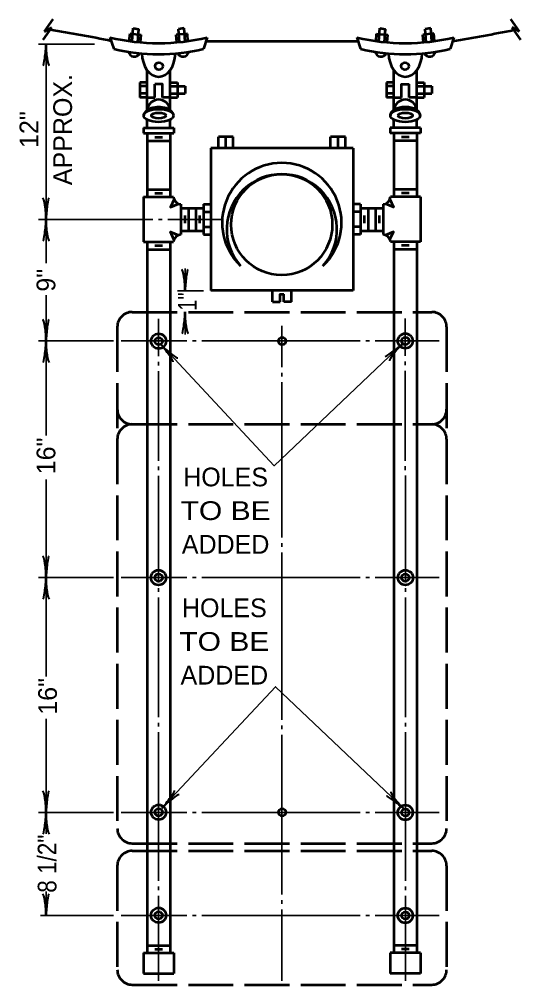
# Model space of a CAD drawing. Extents: x -1 to 679, y 1 to 441.
# Drawn here: x 144.6 to 211.6, y 193.8 to 322.8 of the extents above; entities that cross this region are included whole.
import ezdxf
from ezdxf.enums import TextEntityAlignment as Align

# ---------------------------------------------------------------- set-up
doc = ezdxf.new("R2010")
doc.units = 0
doc.linetypes.add('LONG_DASHED', pattern=[7.5, 6, -1.5])
doc.layers.add('1', color=7, linetype='Continuous', lineweight=35)

msp = doc.modelspace()

# ---------------------------------------------------------------- linework, layer by layer
at = {"layer": '1', "lineweight": 53}
for p, q in [((147.985, 321.145), (149.132, 322.783)), ((211.459, 321.145), (210.311, 322.783)), ((147.833, 320.046), (148.98, 321.684)), ((147.985, 321.145), (148.98, 321.684)), ((159.704, 319.867), (159.857, 321.61)), ((159.857, 321.61), (160.582, 321.469)), ((160.46, 319.723), (160.582, 321.469)), ((166.662, 321.582), (165.909, 321.467)), ((166.031, 319.721), (165.909, 321.467)), ((166.784, 319.836), (166.662, 321.582)), ((192.66, 319.836), (192.782, 321.582)), ((192.782, 321.582), (193.534, 321.467)), ((193.413, 319.721), (193.534, 321.467)), ((199.587, 321.61), (198.862, 321.469)), ((198.983, 319.723), (198.862, 321.469)), ((199.739, 319.867), (199.587, 321.61)), ((211.611, 320.046), (210.464, 321.684)), ((211.459, 321.145), (210.464, 321.684)), ((156.744, 320.356), (157.244, 318.856)), ((159.328, 319.875), (159.418, 320.896)), ((159.418, 320.896), (160.904, 320.695)), ((160.835, 319.707), (160.904, 320.695)), ((167.088, 320.86), (165.587, 320.692)), ((165.656, 319.708), (165.587, 320.692)), ((167.157, 319.875), (167.088, 320.86)), ((169.744, 320.356), (169.244, 318.856)), ((189.699, 320.356), (190.199, 318.856)), ((192.286, 319.875), (192.355, 320.86)), ((192.355, 320.86), (193.856, 320.692)), ((193.787, 319.708), (193.856, 320.692)), ((200.026, 320.896), (198.54, 320.695)), ((198.608, 319.707), (198.54, 320.695)), ((200.115, 319.875), (200.026, 320.896)), ((202.699, 320.356), (202.199, 318.856)), ((169.586, 319.881), (189.857, 319.881)), ((161.722, 310.652), (161.722, 315.963)), ((164.767, 310.652), (164.767, 315.963)), ((194.677, 310.652), (194.677, 315.963)), ((197.722, 310.652), (197.722, 315.963)), ((161.722, 314.356), (160.722, 314.356)), ((160.722, 314.356), (160.722, 312.356)), ((161.722, 313.856), (160.722, 313.856)), ((162.722, 312.356), (162.722, 314.106)), ((164.767, 314.356), (165.767, 314.356)), ((164.767, 313.856), (166.767, 313.856)), ((165.767, 314.356), (165.767, 312.356)), ((166.767, 313.856), (166.767, 312.856)), ((194.677, 314.356), (193.677, 314.356)), ((193.677, 314.356), (193.677, 312.356)), ((194.677, 313.856), (193.677, 313.856)), ((196.722, 312.356), (196.722, 314.106)), ((197.722, 314.356), (198.722, 314.356)), ((197.722, 313.856), (199.722, 313.856)), ((198.722, 314.356), (198.722, 312.356)), ((199.722, 313.856), (199.722, 312.856)), ((161.722, 312.856), (160.722, 312.856)), ((161.722, 312.356), (160.722, 312.356)), ((161.722, 312.356), (162.722, 312.356)), ((164.767, 312.356), (163.767, 312.356)), ((164.767, 312.856), (166.767, 312.856)), ((164.767, 312.356), (165.767, 312.356)), ((194.677, 312.856), (193.677, 312.856)), ((194.677, 312.356), (193.677, 312.356)), ((194.677, 312.356), (195.677, 312.356)), ((197.722, 312.356), (196.722, 312.356)), ((197.722, 312.856), (199.722, 312.856)), ((197.722, 312.356), (198.722, 312.356)), ((161.222, 308.298), (165.267, 308.298)), ((161.222, 308.298), (161.222, 307.548)), ((161.722, 308.298), (161.722, 309.356)), ((164.767, 308.298), (164.767, 309.356)), ((165.267, 308.298), (165.267, 307.548)), ((198.222, 308.298), (194.177, 308.298)), ((194.177, 308.298), (194.177, 307.548)), ((194.677, 308.298), (194.677, 309.356)), ((197.722, 308.298), (197.722, 309.356)), ((198.222, 308.298), (198.222, 307.548)), ((161.222, 307.548), (165.267, 307.548)), ((161.722, 307.548), (161.722, 299.048)), ((162.722, 307.048), (163.767, 307.048)), ((164.767, 307.548), (164.767, 299.048)), ((171.222, 305.57), (171.222, 307.07)), ((173.222, 307.07), (171.222, 307.07)), ((172.222, 305.57), (172.222, 307.07)), ((173.222, 305.57), (173.222, 307.07)), ((186.222, 305.57), (186.222, 307.07)), ((188.222, 307.07), (186.222, 307.07)), ((187.222, 305.57), (187.222, 307.07)), ((188.222, 305.57), (188.222, 307.07)), ((198.222, 307.548), (194.177, 307.548)), ((194.677, 307.548), (194.677, 299.048)), ((196.722, 307.048), (195.677, 307.048)), ((197.722, 307.548), (197.722, 299.048)), ((161.722, 306.548), (164.767, 306.548)), ((197.722, 306.548), (194.677, 306.548)), ((189.222, 305.57), (170.222, 305.57)), ((170.222, 305.57), (170.222, 286.536)), ((189.222, 305.57), (189.222, 286.536)), ((161.722, 300.048), (164.767, 300.048)), ((162.722, 299.548), (163.767, 299.548)), ((197.722, 300.048), (194.677, 300.048)), ((196.722, 299.548), (195.677, 299.548)), ((161.222, 299.048), (165.221, 299.048)), ((161.222, 299.048), (161.222, 293.048)), ((166.222, 298.07), (166.222, 294.025)), ((169.222, 298.07), (169.222, 294.036)), ((169.222, 298.07), (170.222, 298.07)), ((190.222, 298.07), (189.222, 298.07)), ((190.222, 298.07), (190.222, 294.036)), ((193.222, 298.07), (193.222, 294.025)), ((198.222, 299.048), (194.223, 299.048)), ((198.222, 299.048), (198.222, 293.048)), ((166.222, 297.57), (169.222, 297.57)), ((167.222, 297.57), (167.222, 294.525)), ((168.222, 297.57), (168.222, 294.525)), ((169.222, 297.07), (170.222, 297.07)), ((190.222, 297.07), (189.222, 297.07)), ((190.222, 297.57), (193.222, 297.57)), ((191.222, 297.57), (191.222, 294.525)), ((192.222, 297.57), (192.222, 294.525)), ((166.722, 296.57), (166.722, 295.525)), ((168.722, 296.57), (168.722, 295.525)), ((190.722, 296.57), (190.722, 295.525)), ((192.722, 296.57), (192.722, 295.525)), ((166.222, 294.525), (169.222, 294.525)), ((169.222, 295.036), (170.222, 295.036)), ((190.222, 295.036), (189.222, 295.036)), ((190.222, 294.525), (193.222, 294.525)), ((161.222, 293.048), (165.217, 293.048)), ((161.722, 293.048), (164.767, 293.048)), ((164.767, 293.048), (164.767, 283.672)), ((169.222, 294.036), (170.222, 294.036)), ((190.222, 294.036), (189.222, 294.036)), ((198.222, 293.048), (194.226, 293.048)), ((197.722, 293.048), (194.677, 293.048)), ((197.722, 293.048), (197.722, 255.048)), ((161.722, 292.048), (164.767, 292.048)), ((162.722, 292.548), (163.767, 292.548)), ((197.722, 292.048), (194.677, 292.048)), ((196.722, 292.548), (195.677, 292.548)), ((189.222, 286.536), (170.222, 286.536)), ((178.472, 285.036), (178.472, 286.536)), ((180.972, 285.036), (180.972, 286.536)), ((179.972, 285.036), (179.972, 286.036)), ((178.472, 285.036), (179.472, 285.036)), ((180.972, 285.036), (179.972, 285.036)), ((164.767, 283.672), (164.767, 212.672)), ((197.722, 255.048), (197.722, 198.048)), ((164.767, 212.672), (164.767, 198.048)), ((161.722, 199.048), (164.767, 199.048)), ((197.722, 199.048), (194.677, 199.048)), ((161.222, 198.048), (165.267, 198.048)), ((161.222, 198.048), (161.222, 195.298)), ((162.722, 198.548), (163.767, 198.548)), ((165.267, 198.048), (165.267, 195.298)), ((194.177, 198.048), (194.177, 195.298)), ((198.222, 198.048), (194.177, 198.048)), ((196.722, 198.548), (195.677, 198.548)), ((198.222, 198.048), (198.222, 195.298)), ((161.222, 195.298), (165.267, 195.298)), ((198.222, 195.298), (194.177, 195.298))]:
    msp.add_line(p, q, dxfattribs=at)
at = {"layer": '1'}
for p, q in [((154.674, 319.477), (147.199, 319.477)), ((148.199, 296.048), (148.199, 319.477)), ((162.472, 296.048), (147.199, 296.048)), ((148.199, 296.048), (148.199, 290.214)), ((163.222, 296.048), (163.722, 296.048)), ((164.472, 296.048), (171.738, 296.048)), ((166.767, 286.492), (166.767, 289.492)), ((165.767, 286.492), (169.222, 286.492)), ((163.244, 282.781), (163.244, 277.781)), ((166.767, 283.672), (166.767, 280.672)), ((196.199, 282.809), (196.199, 277.809)), ((179.722, 281.814), (179.722, 276.289)), ((147.199, 279.814), (157.222, 279.814)), ((158.222, 279.814), (167.017, 279.814)), ((166.517, 279.814), (167.017, 279.814)), ((167.767, 279.814), (168.267, 279.814)), ((169.017, 279.814), (190.177, 279.814)), ((190.927, 279.814), (191.427, 279.814)), ((192.177, 279.814), (200.722, 279.814)), ((163.244, 277.031), (163.244, 276.531)), ((196.199, 277.059), (196.199, 276.559)), ((163.244, 275.781), (163.244, 263.781)), ((179.722, 275.039), (179.722, 275.539)), ((196.199, 275.809), (196.199, 263.809)), ((179.722, 274.289), (179.722, 253.548)), ((163.244, 263.031), (163.244, 262.531)), ((196.199, 263.059), (196.199, 262.559)), ((163.221, 261.781), (163.221, 247.542)), ((196.222, 261.809), (196.222, 247.542)), ((179.722, 252.298), (179.722, 252.798)), ((179.722, 251.548), (179.722, 229.193)), ((157.222, 248.193), (147.199, 248.193)), ((158.222, 248.193), (167.017, 248.193)), ((167.767, 248.193), (168.267, 248.193)), ((169.017, 248.193), (190.177, 248.193)), ((190.927, 248.193), (191.427, 248.193)), ((200.722, 248.193), (192.177, 248.193)), ((200.722, 248.193), (192.722, 248.193)), ((163.221, 246.792), (163.221, 246.292)), ((196.222, 246.792), (196.222, 246.292)), ((163.221, 245.542), (163.221, 229.542)), ((196.222, 245.542), (196.222, 229.542)), ((163.221, 228.792), (163.221, 228.292)), ((179.722, 227.943), (179.722, 228.443)), ((196.222, 228.792), (196.222, 228.292)), ((163.221, 227.542), (163.221, 207.672)), ((179.722, 227.193), (179.722, 205.825)), ((196.222, 227.542), (196.222, 207.672)), ((147.199, 216.799), (157.222, 216.799)), ((158.222, 216.799), (167.017, 216.799)), ((167.767, 216.799), (168.267, 216.799)), ((169.017, 216.799), (190.177, 216.799)), ((190.927, 216.799), (191.427, 216.799)), ((192.177, 216.799), (200.722, 216.799)), ((179.722, 212.292), (179.722, 212.792)), ((163.221, 206.422), (163.221, 206.922)), ((196.222, 206.422), (196.222, 206.922)), ((148.199, 206.256), (148.199, 203.048)), ((163.221, 205.672), (163.221, 194.298)), ((196.222, 205.672), (196.222, 194.298)), ((179.722, 205.075), (179.722, 204.575)), ((179.722, 203.825), (179.722, 194.298)), ((157.222, 203.048), (147.449, 203.048)), ((158.222, 203.048), (167.017, 203.048)), ((167.767, 203.048), (168.267, 203.048)), ((169.017, 203.048), (190.177, 203.048)), ((190.927, 203.048), (191.427, 203.048)), ((192.177, 203.048), (200.722, 203.048))]:
    msp.add_line(p, q, dxfattribs=at)
at = {"layer": '1', "linetype": 'LONG_DASHED', "lineweight": 53}
for p, q in [((159.722, 283.672), (199.722, 283.672)), ((157.722, 281.672), (157.722, 266.672)), ((201.722, 281.672), (201.722, 266.672)), ((159.722, 268.672), (199.722, 268.672)), ((157.722, 266.672), (157.722, 214.672)), ((201.722, 266.672), (201.722, 214.672)), ((159.722, 212.672), (199.722, 212.672)), ((159.722, 211.672), (199.722, 211.672)), ((157.722, 209.672), (157.722, 195.793)), ((201.722, 209.672), (201.722, 195.793)), ((159.722, 193.793), (199.722, 193.793))]:
    msp.add_line(p, q, dxfattribs=at)
at = {"layer": '1', "lineweight": 13}
for p, q in [((179.722, 212.792), (179.722, 213.542)), ((179.722, 211.542), (179.722, 212.292))]:
    msp.add_line(p, q, dxfattribs=at)
at = {"layer": '1', "lineweight": 53}
for points in [[(163.767, 312.356), (163.767, 314.106), (162.722, 314.106)], [(195.677, 312.356), (195.677, 314.106), (196.722, 314.106)], [(165.299, 298.745), (164.814, 297.698), (165.905, 298.146)], [(194.145, 298.745), (194.63, 297.698), (193.538, 298.146)], [(165.295, 293.35), (164.81, 294.397), (165.902, 293.949)], [(194.148, 293.35), (194.633, 294.397), (193.542, 293.949)], [(161.722, 293.048), (161.722, 255.048), (161.722, 198.048)], [(194.677, 293.048), (194.677, 255.048), (194.677, 198.048)], [(179.472, 285.036), (179.472, 286.036), (179.972, 286.036)]]:
    msp.add_lwpolyline(points, dxfattribs=at)
at = {"layer": '1'}
for points in [[(148.199, 285.903), (148.199, 279.814), (148.199, 267.186)], [(163.525, 279.364), (178.678, 263.127), (195.867, 279.448)], [(148.199, 261.306), (148.199, 248.193), (148.199, 234.971)], [(163.689, 217.363), (178.842, 233.6), (196.031, 217.278)], [(148.199, 229.324), (148.199, 216.799), (148.199, 213.945)]]:
    msp.add_lwpolyline(points, dxfattribs=at)
at = {"layer": '1', "lineweight": 53}
for centre, radius in [((163.289, 316.528), 0.5), ((196.155, 316.528), 0.5), ((179.691, 295.35), 6.75), ((163.235, 279.781), 1), ((163.249, 279.781), 0.5), ((179.746, 279.789), 0.5), ((196.198, 279.809), 1), ((196.213, 279.809), 0.5), ((163.226, 248.186), 1), ((196.218, 248.186), 1), ((163.241, 248.186), 0.5), ((196.203, 248.186), 0.5), ((163.235, 216.832), 1), ((163.249, 216.832), 0.5), ((179.746, 216.825), 0.5), ((196.198, 216.804), 1), ((196.213, 216.804), 0.5), ((163.229, 203.061), 1), ((196.197, 203.038), 1), ((163.244, 203.061), 0.5), ((196.211, 203.038), 0.5)]:
    msp.add_circle(centre, radius, dxfattribs=at)
for centre, radius, start, end in [((126.005, 172.228), 150.851, 78.18089, 81.33006), ((160.338, 576.7), 260.264, 279.33196, 281.15709), ((163.244, 348.147), 28.542, 256.83593, 283.1638), ((196.199, 348.147), 28.542, 256.8362, 283.16407), ((163.244, 342.481), 24.375, 255.74997, 284.25003), ((196.199, 342.481), 24.375, 255.74997, 284.25003), ((160.006, 318.618), 0.821, 192.33045, 332.21364), ((166.485, 318.618), 0.821, 207.78636, 347.66955), ((192.958, 318.618), 0.821, 192.33045, 332.21364), ((199.438, 318.618), 0.821, 207.78636, 347.66955), ((163.244, 310.52), 1.528, 4.98578, 175.01422), ((196.199, 310.52), 1.528, 4.98578, 175.01422), ((179.701, 295.614), 7.975, 313.60282, 226.39718), ((179.701, 294.736), 7.364, 318.31863, 221.68137), ((166.317, 299.169), 1.103, 186.32364, 248.08344), ((166.317, 299.169), 1.103, 202.62687, 248.08262), ((166.317, 299.169), 1.103, 248.08344, 265.0377), ((193.126, 299.169), 1.103, 274.9623, 291.91656), ((193.126, 299.169), 1.103, 291.91656, 353.67636), ((193.126, 299.169), 1.103, 291.91738, 337.37313), ((166.314, 292.926), 1.103, 111.91656, 173.65459), ((166.314, 292.926), 1.103, 111.91738, 157.37313), ((166.314, 292.926), 1.103, 94.77118, 111.91656), ((193.13, 292.926), 1.103, 68.08344, 85.22882), ((193.13, 292.926), 1.103, 6.34541, 68.08344), ((193.13, 292.926), 1.103, 22.62687, 68.08262)]:
    msp.add_arc(centre, radius, start, end, dxfattribs=at)
at = {"layer": '1', "linetype": 'LONG_DASHED', "lineweight": 53}
for centre, start, end in [((159.722, 281.672), 90, 180), ((199.722, 281.672), 0, 90), ((159.722, 270.672), 180, 270), ((199.722, 270.672), 270, 0), ((159.722, 266.672), 90, 180), ((199.722, 266.672), 0, 90), ((159.722, 214.672), 180, 270), ((159.722, 214.672), 180, 270), ((199.722, 214.672), 270, 0), ((159.722, 209.672), 90, 180), ((199.722, 209.672), 0, 90), ((159.722, 195.793), 180, 270), ((199.722, 195.793), 270, 0)]:
    msp.add_arc(centre, 2, start, end, dxfattribs=at)
at = {"layer": '1', "lineweight": 40}
for centre, major_axis, ratio, start_param, end_param in [((147.988, 318.357), (0.176, 1.756), 0.07063, 3.1407148, 5.41811), ((147.988, 318.357), (0.176, 1.756), 0.07063, 3.1407148, 5.41811), ((148.475, 318.386), (-0.156, 1.786), 0.122415, 0.8963533, 3.1415927), ((148.475, 318.386), (-0.156, 1.786), 0.122415, 0.8963533, 3.1415927), ((147.923, 297.139), (0.156, -1.786), 0.122415, 0.8963533, 3.1415927), ((147.923, 297.139), (0.156, -1.786), 0.122415, 0.8963533, 3.1415927), ((148.411, 297.168), (-0.176, -1.756), 0.07063, 3.1407148, 5.41811), ((148.411, 297.168), (-0.176, -1.756), 0.07063, 3.1407148, 5.41811), ((147.988, 294.927), (0.176, 1.756), 0.07063, 3.1407148, 5.41811), ((147.988, 294.927), (0.176, 1.756), 0.07063, 3.1407148, 5.41811), ((148.475, 294.957), (-0.156, 1.786), 0.122415, 0.8963533, 3.1415927), ((148.475, 294.957), (-0.156, 1.786), 0.122415, 0.8963533, 3.1415927), ((166.491, 287.583), (0.156, -1.786), 0.122415, 0.8963533, 3.1415927), ((166.978, 287.613), (-0.176, -1.756), 0.07063, 3.1407148, 5.41811), ((147.923, 280.905), (0.156, -1.786), 0.122415, 0.8963533, 3.1415927), ((147.923, 280.905), (0.156, -1.786), 0.122415, 0.8963533, 3.1415927), ((148.411, 280.935), (-0.176, -1.756), 0.07063, 3.1407148, 5.41811), ((148.411, 280.935), (-0.176, -1.756), 0.07063, 3.1407148, 5.41811), ((166.555, 282.552), (0.176, 1.756), 0.07063, 3.1407148, 5.41811), ((167.043, 282.581), (-0.156, 1.786), 0.122415, 0.8963533, 3.1415927), ((147.988, 278.693), (0.176, 1.756), 0.07063, 3.1407148, 5.41811), ((147.988, 278.693), (0.176, 1.756), 0.07063, 3.1407148, 5.41811), ((148.475, 278.723), (-0.156, 1.786), 0.122415, 0.8963533, 3.1415927), ((148.475, 278.723), (-0.156, 1.786), 0.122415, 0.8963533, 3.1415927), ((164.135, 278.4), (-1.07, 1.404), 0.07063, 3.1407148, 5.41811), ((164.135, 278.4), (-1.07, 1.404), 0.07063, 3.1407148, 5.41811), ((164.471, 278.755), (-1.333, 1.199), 0.122415, 0.8963533, 3.1415927), ((164.471, 278.755), (-1.333, 1.199), 0.122415, 0.8963533, 3.1415927), ((194.909, 278.83), (-1.395, -1.082), 0.07063, 6.2823074, 8.5597026), ((195.266, 278.497), (1.187, 1.343), 0.122415, 0.8963533, 3.1415927), ((147.923, 249.284), (0.156, -1.786), 0.122415, 0.8963533, 3.1415927), ((147.923, 249.284), (0.156, -1.786), 0.122415, 0.8963533, 3.1415927), ((148.411, 249.313), (-0.176, -1.756), 0.07063, 3.1407148, 5.41811), ((148.411, 249.313), (-0.176, -1.756), 0.07063, 3.1407148, 5.41811), ((147.988, 247.072), (0.176, 1.756), 0.07063, 3.1407148, 5.41811), ((147.988, 247.072), (0.176, 1.756), 0.07063, 3.1407148, 5.41811), ((148.475, 247.101), (-0.156, 1.786), 0.122415, 0.8963533, 3.1415927), ((148.475, 247.101), (-0.156, 1.786), 0.122415, 0.8963533, 3.1415927), ((147.923, 217.891), (0.156, -1.786), 0.122415, 0.8963533, 3.1415927), ((148.411, 217.92), (-0.176, -1.756), 0.07063, 3.1407148, 5.41811), ((164.298, 218.326), (-1.07, -1.404), 0.07063, 0.8650754, 3.1424706), ((164.298, 218.326), (-1.07, -1.404), 0.07063, 0.8650754, 3.1424706), ((195.43, 218.23), (1.187, -1.343), 0.122415, 3.1415927, 5.386832), ((164.635, 217.972), (-1.333, -1.199), 0.122415, 3.1415927, 5.386832), ((164.635, 217.972), (-1.333, -1.199), 0.122415, 3.1415927, 5.386832), ((195.073, 217.896), (-1.395, 1.082), 0.07063, 4.006668, 6.2840632), ((147.988, 215.679), (0.176, 1.756), 0.07063, 3.1407148, 5.41811), ((147.988, 215.679), (0.176, 1.756), 0.07063, 3.1407148, 5.41811), ((148.475, 215.708), (-0.156, 1.786), 0.122415, 0.8963533, 3.1415927), ((148.475, 215.708), (-0.156, 1.786), 0.122415, 0.8963533, 3.1415927), ((147.923, 204.139), (0.156, -1.786), 0.122415, 0.8963533, 3.1415927), ((147.923, 204.139), (0.156, -1.786), 0.122415, 0.8963533, 3.1415927), ((148.411, 204.168), (-0.176, -1.756), 0.07063, 3.1407148, 5.41811), ((148.411, 204.168), (-0.176, -1.756), 0.07063, 3.1407148, 5.41811)]:
    msp.add_ellipse(centre, major_axis=major_axis, ratio=ratio, start_param=start_param, end_param=end_param, dxfattribs=at)
at = {"layer": '1', "lineweight": 53}
for centre, major_axis, ratio, start_param, end_param in [((163.244, 318.356), (0, 3.25), 0.692308, 1.615522, 4.6676498), ((196.199, 318.356), (0, 3.25), 0.692308, 1.6155355, 4.6676633), ((163.244, 309.923), (2, 0), 0.5625, 6.2831853, 9.424778), ((196.199, 309.923), (-2, 0), 0.5625, 3.1415927, 6.2831853)]:
    msp.add_ellipse(centre, major_axis=major_axis, ratio=ratio, start_param=start_param, end_param=end_param, dxfattribs=at)
for centre, major_axis, ratio in [((163.244, 309.923), (2, 0), 0.4375), ((163.244, 309.923), (1, 0), 0.375), ((196.199, 309.923), (-2, 0), 0.4375), ((196.199, 309.923), (-1, 0), 0.375)]:
    msp.add_ellipse(centre, major_axis=major_axis, ratio=ratio, dxfattribs=at)

# ---------------------------------------------------------------- texts
at = {"layer": '1'}
for s, p in [('APPROX.', (151.668, 308.049)), ('12"', (147.168, 308.049))]:
    msp.add_text(s, height=2.5, rotation=90, dxfattribs=at).set_placement(p, align=Align.CENTER)
for s, p in [('9"', (149.442, 286.393)), ('16"', (149.442, 261.992)), ('16"', (149.652, 229.864))]:
    msp.add_text(s, height=2.5, rotation=90, dxfattribs=at).set_placement(p)
for s, width, p in [('1"', 0.8, (168.313, 283.846)), ('8 1/2"', 0.9, (149.592, 206.076))]:
    msp.add_text(s, height=2.5, rotation=90, dxfattribs=dict(at, width=width)).set_placement(p)
for s, p in [('HOLES', (172.192, 260.383)), ('ADDED', (172.192, 251.383)), ('HOLES', (172.021, 242.899)), ('ADDED', (172.021, 233.899))]:
    msp.add_text(s, height=2.5, dxfattribs=at).set_placement(p, align=Align.CENTER)
at = {"layer": '1', "width": 1.2}
for p in [(172.192, 255.883), (172.02, 238.399)]:
    msp.add_text('TO BE', height=2.5, dxfattribs=at).set_placement(p, align=Align.CENTER)

doc.saveas('drawing.dxf')
